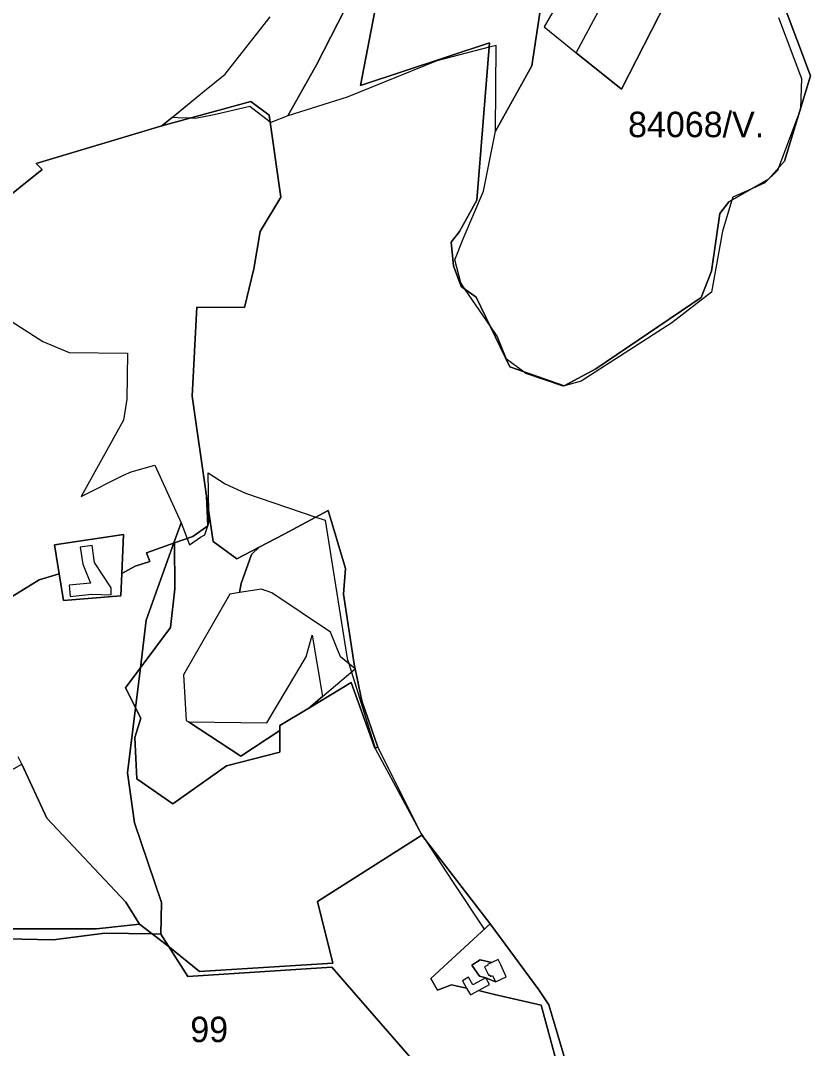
# Model space of a CAD drawing. Extents: x -477304 to -465429, y -1159113 to -1149210.
# Drawn here: x -476121 to -475655, y -1151065 to -1150459 of the extents above; entities that cross this region are included whole.
import ezdxf

# ---------------------------------------------------------------- set-up
doc = ezdxf.new("R2010")
doc.units = 0
for name, color, linetype in [('BPEJ_s', 7, 'Continuous'), ('PUPFL_s', 7, 'Continuous'), ('trav_porost_s', 7, 'Continuous'), ('zahrada_s', 7, 'Continuous')]:
    doc.layers.add(name, color=color, linetype=linetype)

msp = doc.modelspace()

# ---------------------------------------------------------------- linework, layer by layer
at = {"layer": 'BPEJ_s'}
msp.add_lwpolyline([(-475798.5, -1150405.5), (-475803.5, -1150423), (-475813, -1150445.5), (-475819, -1150486), (-475840.5, -1150524.5), (-475840, -1150474), (-475844.18, -1150475.08), (-475875, -1150483), (-475928, -1150504.5), (-475963, -1150515.5), (-475946, -1150485.5), (-475921, -1150436), (-475904.5, -1150387), (-475857.5, -1150197.5), (-475852, -1150163), (-475844.5, -1150157), (-475825.39, -1150276.94), (-475806.53, -1150395.32), (-475806.5, -1150395.5), (-475805.69, -1150404.36), (-475805.5, -1150406.5)], close=True, dxfattribs=at)
for points in [[(-475921, -1150436), (-475946, -1150485.5), (-475963, -1150515.5), (-475973, -1150519.5), (-475973.46, -1150519.15), (-475985.5, -1150510), (-476006.5, -1150515), (-476017.5, -1150517), (-476020.79, -1150516.87), (-476027.8, -1150516.59), (-476030, -1150516.5), (-476031.23, -1150516.42), (-476012.21, -1150500.78), (-475999.97, -1150491.01), (-475973.45, -1150457.17)], [(-475673.5, -1150457.5), (-475660, -1150493.5), (-475660.48, -1150510.93), (-475660.5, -1150511.5), (-475661.35, -1150513.76), (-475673.52, -1150546.23), (-475674, -1150547.5), (-475681.5, -1150555), (-475689.27, -1150558.48), (-475700.5, -1150563.5), (-475701, -1150565.16), (-475706.5, -1150583.5), (-475713, -1150619.5), (-475736.5, -1150637.5), (-475790, -1150672), (-475800.5, -1150675), (-475822.5, -1150667.5), (-475824.3, -1150666.17), (-475834, -1150659), (-475839.5, -1150645.5), (-475843.66, -1150639.4), (-475858.37, -1150617.85), (-475861, -1150614), (-475864.5, -1150600.5), (-475859.5, -1150588), (-475847.5, -1150560), (-475840.5, -1150524.5), (-475819, -1150486), (-475813, -1150445.5)], [(-475673.5, -1150457.5), (-475660, -1150493.5), (-475660.48, -1150510.93), (-475660.5, -1150511.5), (-475661.35, -1150513.76), (-475673.52, -1150546.23), (-475674, -1150547.5), (-475681.5, -1150555), (-475689.27, -1150558.48), (-475700.5, -1150563.5), (-475701, -1150565.16), (-475706.5, -1150583.5), (-475713, -1150619.5), (-475736.5, -1150637.5), (-475790, -1150672), (-475800.5, -1150675), (-475822.5, -1150667.5), (-475824.3, -1150666.17), (-475834, -1150659), (-475839.5, -1150645.5), (-475843.66, -1150639.4), (-475858.37, -1150617.85), (-475861, -1150614), (-475864.5, -1150600.5), (-475859.5, -1150588), (-475847.5, -1150560), (-475840.5, -1150524.5), (-475840, -1150474), (-475844.18, -1150475.08), (-475875, -1150483), (-475928, -1150504.5), (-475963, -1150515.5), (-475973, -1150519.5), (-475973.46, -1150519.15), (-475985.5, -1150510), (-476006.5, -1150515), (-476017.5, -1150517), (-476020.79, -1150516.87), (-476027.8, -1150516.59), (-476030, -1150516.5), (-476031.23, -1150516.42), (-476037.3, -1150521.41), (-476111.52, -1150543.57), (-476107.95, -1150547.2), (-476135.12, -1150568.82)], [(-476150.5, -1150621), (-476107.5, -1150648.5), (-476092, -1150655), (-476057.5, -1150655.5), (-476058, -1150682.5), (-476060, -1150695), (-476085, -1150740), (-476060, -1150727.5), (-476055.5, -1150725.5), (-476041.5, -1150721.5), (-476026, -1150755.5), (-476030.23, -1150767.36), (-476046.5, -1150813), (-476049.92, -1150840.95), (-476052.81, -1150864.64), (-476057.5, -1150903), (-476053.5, -1150932.5), (-476037.5, -1150979.5), (-476038, -1150998), (-476042.94, -1150997.93), (-476071, -1150997.5), (-476101.5, -1151001.5), (-476148.03, -1151000.51)], [(-476150.5, -1150621), (-476107.5, -1150648.5), (-476092, -1150655), (-476057.5, -1150655.5), (-476058, -1150682.5), (-476060, -1150695), (-476085, -1150740), (-476060, -1150727.5), (-476055.5, -1150725.5), (-476041.5, -1150721.5), (-476026, -1150755.5), (-476022.45, -1150764.73), (-476021, -1150768.5), (-476014.5, -1150764), (-476012, -1150762.5), (-476009.5, -1150755.5), (-476009.6, -1150749.35), (-476010, -1150726), (-476000, -1150732.5), (-475988, -1150738), (-475946.45, -1150752.14)], [(-476009.6, -1150749.35), (-476010, -1150726), (-476000, -1150732.5), (-475988, -1150738), (-475946.45, -1150752.14), (-475941, -1150754), (-475928, -1150835.5), (-475927.06, -1150838.52), (-475925.51, -1150843.49), (-475911.53, -1150888.41), (-475911.5, -1150888.5), (-475885.66, -1150936.34), (-475884.5, -1150938.5), (-475882.17, -1150942.03), (-475865.75, -1150966.96), (-475847.12, -1150995.23), (-475843.55, -1150991.95), (-475814.94, -1151030.96), (-475808.91, -1151039.84), (-475796.84, -1151080.93)], [(-475887, -1151075), (-475937, -1151017.5), (-476022, -1151023), (-476033.39, -1151005.21), (-476038, -1150998), (-476037.5, -1150979.5), (-476053.5, -1150932.5), (-476057.5, -1150903), (-476052.81, -1150864.64), (-476049.92, -1150840.95), (-476046.5, -1150813), (-476030.23, -1150767.36), (-476026, -1150755.5), (-476022.45, -1150764.73), (-476021, -1150768.5), (-476014.5, -1150764), (-476012, -1150762.5), (-476009.5, -1150755.5), (-476009.6, -1150749.35)], [(-475946.45, -1150752.14), (-475941, -1150754), (-475928, -1150835.5), (-475927.06, -1150838.52), (-475925.51, -1150843.49), (-475911.53, -1150888.41), (-475911.5, -1150888.5), (-475885.66, -1150936.34), (-475884.5, -1150938.5), (-475882.17, -1150942.03), (-475865.75, -1150966.96), (-475847.12, -1150995.23), (-475843.55, -1150991.95), (-475814.94, -1151030.96), (-475808.91, -1151039.84), (-475796.84, -1151080.93)], [(-476148.03, -1151000.51), (-476101.5, -1151001.5), (-476071, -1150997.5), (-476042.94, -1150997.93), (-476038, -1150998), (-476033.39, -1151005.21), (-476022, -1151023), (-475937, -1151017.5), (-475887, -1151075), (-475896.5, -1151095), (-475909, -1151113), (-475910.5, -1151126), (-475916.5, -1151118.5), (-475923.44, -1151106.06), (-475928.5, -1151097), (-475929.78, -1151094.97), (-475940.5, -1151078), (-475993.5, -1151088.5), (-476005.94, -1151090.56), (-476099, -1151106), (-476112.2, -1151106), (-476116, -1151106), (-476139, -1151069)]]:
    msp.add_lwpolyline(points, dxfattribs=at)
at = {"layer": 'PUPFL_s'}
for points in [[(-475901.25, -1150399.47), (-475920.09, -1150497.65), (-475843.96, -1150472.36), (-475851.53, -1150565.21), (-475861.68, -1150583.63), (-475866.66, -1150589.92), (-475865.32, -1150604.05), (-475860.75, -1150616.16), (-475851.8, -1150622.53), (-475832.06, -1150663.46), (-475799.98, -1150674.66), (-475781.24, -1150664.79), (-475719.05, -1150622.69), (-475713.08, -1150607.03), (-475708.1, -1150573.12), (-475702.86, -1150566.22), (-475679.38, -1150552.84), (-475670.05, -1150542.31), (-475654.66, -1150491.82), (-475670.75, -1150449.11)], [(-475670.75, -1150449.11), (-475654.66, -1150491.82), (-475670.05, -1150542.31), (-475679.38, -1150552.84), (-475702.86, -1150566.22), (-475708.1, -1150573.12), (-475713.08, -1150607.03), (-475719.05, -1150622.69), (-475781.24, -1150664.79), (-475799.98, -1150674.66), (-475832.06, -1150663.46), (-475851.8, -1150622.53), (-475860.75, -1150616.16), (-475865.32, -1150604.05), (-475866.66, -1150589.92), (-475861.68, -1150583.63), (-475851.53, -1150565.21), (-475843.96, -1150472.36), (-475920.09, -1150497.65), (-475901.25, -1150399.47)], [(-475782.4, -1150412.05), (-475811.82, -1150463.08), (-475792.8, -1150478.3), (-475766.07, -1150499.69), (-475739.67, -1150447.78)], [(-475796.84, -1151080.93), (-475808.91, -1151039.84), (-475814.94, -1151030.96), (-475843.55, -1150991.95), (-475884, -1150939.67), (-475909.96, -1150887.79), (-475919.27, -1150860.49), (-475923.23, -1150841.55), (-475923.78, -1150838.93), (-475930.07, -1150797.52), (-475928.87, -1150782.41), (-475939.22, -1150748.22), (-475965.14, -1150762.28), (-475979.85, -1150769.85), (-475993.17, -1150776.71), (-476007.12, -1150766.55), (-476010.98, -1150739.83), (-476019.52, -1150680.76), (-476016.58, -1150628.43), (-475988.64, -1150628.59), (-475983.13, -1150605.8), (-475979.28, -1150583.65), (-475967.16, -1150563.43), (-475974.03, -1150515.17), (-475984.8, -1150506.97), (-476037.3, -1150521.41), (-476012.21, -1150500.78), (-475999.97, -1150491.01), (-475973.45, -1150457.17)], [(-476135.12, -1150568.82), (-476107.95, -1150547.2), (-476111.52, -1150543.57), (-476037.3, -1150521.41), (-475984.8, -1150506.97), (-475974.03, -1150515.17), (-475967.16, -1150563.43), (-475979.28, -1150583.65), (-475983.13, -1150605.8), (-475988.64, -1150628.59), (-476016.58, -1150628.43), (-476019.52, -1150680.76), (-476010.98, -1150739.83), (-476010.18, -1150757.2), (-476019, -1150763.56), (-476029.9, -1150767.24), (-476046.33, -1150773.27), (-476044.34, -1150778.39), (-476053.04, -1150781.12), (-476060.97, -1150785.31), (-476060, -1150762.3), (-476100.55, -1150768.46), (-476097.84, -1150785.64), (-476109.7, -1150789.06), (-476140.24, -1150807.74)], [(-476140.24, -1150807.74), (-476109.7, -1150789.06), (-476097.84, -1150785.64), (-476095.37, -1150801.28), (-476061.52, -1150798.48), (-476060.97, -1150785.31), (-476053.04, -1150781.12), (-476044.34, -1150778.39), (-476046.33, -1150773.27), (-476029.9, -1150767.24), (-476029.67, -1150794.35), (-476032.16, -1150817.25), (-476058.84, -1150852.86), (-476049.74, -1150870.64), (-476053.29, -1150882.11), (-476052.16, -1150906.55), (-476030.86, -1150921.21), (-475999.26, -1150898.9), (-475967.76, -1150890.69), (-475967.68, -1150878.02), (-475967.66, -1150875.13), (-475950.53, -1150864.74), (-475925.56, -1150849.6), (-475911.57, -1150888.43), (-475909.96, -1150887.79), (-475884, -1150939.67), (-475945.57, -1150978.88), (-475936.34, -1151015.19), (-476015.01, -1151020.2), (-476033.74, -1151004.92), (-476050.49, -1150992.18), (-476058.51, -1150979.19), (-476105.17, -1150929.65), (-476120.01, -1150897.77), (-476122.03, -1150893.44)], [(-476131.48, -1150994.9), (-476075.81, -1150994.87), (-476050.49, -1150992.18), (-476033.74, -1151004.92), (-476015.01, -1151020.2), (-475936.34, -1151015.19), (-475945.57, -1150978.88), (-475884, -1150939.67), (-475843.55, -1150991.95), (-475878.6, -1151024.17), (-475874.62, -1151031.07), (-475866.38, -1151028), (-475857.54, -1151029.86), (-475855.24, -1151033.93), (-475850.53, -1151031.33), (-475841.1, -1151033.65), (-475813.61, -1151040.02), (-475802.65, -1151079.79)]]:
    msp.add_lwpolyline(points, dxfattribs=at)
for points in [[(-476010.98, -1150739.83), (-476007.12, -1150766.55), (-475993.17, -1150776.71), (-475979.85, -1150769.85), (-475984.37, -1150774.23), (-475990.55, -1150791.39), (-475991.45, -1150796.69), (-475997.25, -1150797.59), (-476024.46, -1150845.1), (-476022.92, -1150872.02), (-476021.64, -1150872.86), (-475990.78, -1150893.06), (-475967.68, -1150878.02), (-475967.76, -1150890.69), (-475999.26, -1150898.9), (-476030.86, -1150921.21), (-476052.16, -1150906.55), (-476053.29, -1150882.11), (-476049.74, -1150870.64), (-476058.84, -1150852.86), (-476032.16, -1150817.25), (-476029.67, -1150794.35), (-476029.9, -1150767.24), (-476019, -1150763.56), (-476010.18, -1150757.2)], [(-475978.61, -1150794.71), (-475991.45, -1150796.69), (-475990.55, -1150791.39), (-475984.37, -1150774.23), (-475979.85, -1150769.85), (-475965.14, -1150762.28), (-475939.22, -1150748.22), (-475928.87, -1150782.41), (-475930.07, -1150797.52), (-475923.78, -1150838.93), (-475923.23, -1150841.55), (-475931.98, -1150834.62), (-475937.87, -1150819.99), (-475972.4, -1150796.85)], [(-475909.96, -1150887.79), (-475911.57, -1150888.43), (-475925.56, -1150849.6), (-475950.53, -1150864.74), (-475942.51, -1150857.93), (-475923.23, -1150841.55), (-475919.27, -1150860.49)]]:
    msp.add_lwpolyline(points, close=True, dxfattribs=at)
at = {"layer": 'trav_porost_s'}
for points in [[(-476095.37, -1150801.28), (-476097.84, -1150785.64), (-476100.55, -1150768.46), (-476060, -1150762.3), (-476060.97, -1150785.31), (-476061.52, -1150798.48)], [(-476085.46, -1150769.95), (-476084, -1150779.91), (-476079.38, -1150791.06), (-476092.04, -1150792.33), (-476091.44, -1150798.96), (-476078.78, -1150797.68), (-476067.13, -1150797.94), (-476067.29, -1150793.84), (-476077.04, -1150778.83), (-476078.48, -1150768.93)], [(-475952.14, -1150834.47), (-475948.65, -1150821.74), (-475942.51, -1150857.93), (-475950.53, -1150864.74), (-475967.66, -1150875.13), (-475967.68, -1150878.02), (-475990.78, -1150893.06), (-476021.64, -1150872.86), (-475975.34, -1150873.37)], [(-476291.66, -1150853.44), (-476285.76, -1150853.51), (-476275.15, -1150859.5), (-476248.92, -1150875.23), (-476226.98, -1150891.89), (-476179.52, -1150929.19), (-476169.27, -1150938.5), (-476146.89, -1150917.53), (-476141.2, -1150911.63), (-476128.94, -1150902.85), (-476120.01, -1150897.77), (-476105.17, -1150929.65), (-476058.51, -1150979.19), (-476050.49, -1150992.18), (-476075.81, -1150994.87), (-476131.48, -1150994.9), (-476151.58, -1150982.94), (-476179.85, -1150932.3), (-476197.3, -1150924.8), (-476247.95, -1150880.21)], [(-475842.64, -1151014.84), (-475845.25, -1151016.04), (-475845.06, -1151016.46), (-475846.88, -1151017.36), (-475844.5, -1151022.43), (-475843.91, -1151022.12), (-475843.46, -1151022.99), (-475842.26, -1151022.43), (-475840.56, -1151026.16), (-475846.23, -1151023.91), (-475850, -1151022.92), (-475854.38, -1151016.31), (-475849.58, -1151013.13)]]:
    msp.add_lwpolyline(points, close=True, dxfattribs=at)
msp.add_lwpolyline([(-475802.65, -1151079.79), (-475813.61, -1151040.02), (-475841.1, -1151033.65), (-475850.53, -1151031.33), (-475844.09, -1151027.77), (-475846.23, -1151023.91), (-475840.56, -1151026.16), (-475834.12, -1151023.19), (-475837.42, -1151016.13), (-475838.84, -1151013.09), (-475842.64, -1151014.84), (-475849.58, -1151013.13), (-475854.38, -1151016.31), (-475850, -1151022.92), (-475846.23, -1151023.91), (-475853.78, -1151028.04), (-475856.32, -1151023.47), (-475859.91, -1151025.66), (-475857.54, -1151029.86), (-475866.38, -1151028), (-475874.62, -1151031.07), (-475878.6, -1151024.17), (-475843.55, -1150991.95), (-475814.94, -1151030.96), (-475808.91, -1151039.84), (-475796.84, -1151080.93)], dxfattribs=at)
at = {"layer": 'zahrada_s'}
msp.add_lwpolyline([(-475739.67, -1150447.78), (-475766.07, -1150499.69), (-475792.8, -1150478.3), (-475765.24, -1150426.4)], close=True, dxfattribs=at)

# ---------------------------------------------------------------- texts
at = {"layer": 'BPEJ_s'}
for s, p in [('84068/V.', (-475762.25, -1150528.09)), ('99', (-476020.52, -1151061.75))]:
    msp.add_text(s, height=15, dxfattribs=at).set_placement(p)

doc.saveas('drawing.dxf')
